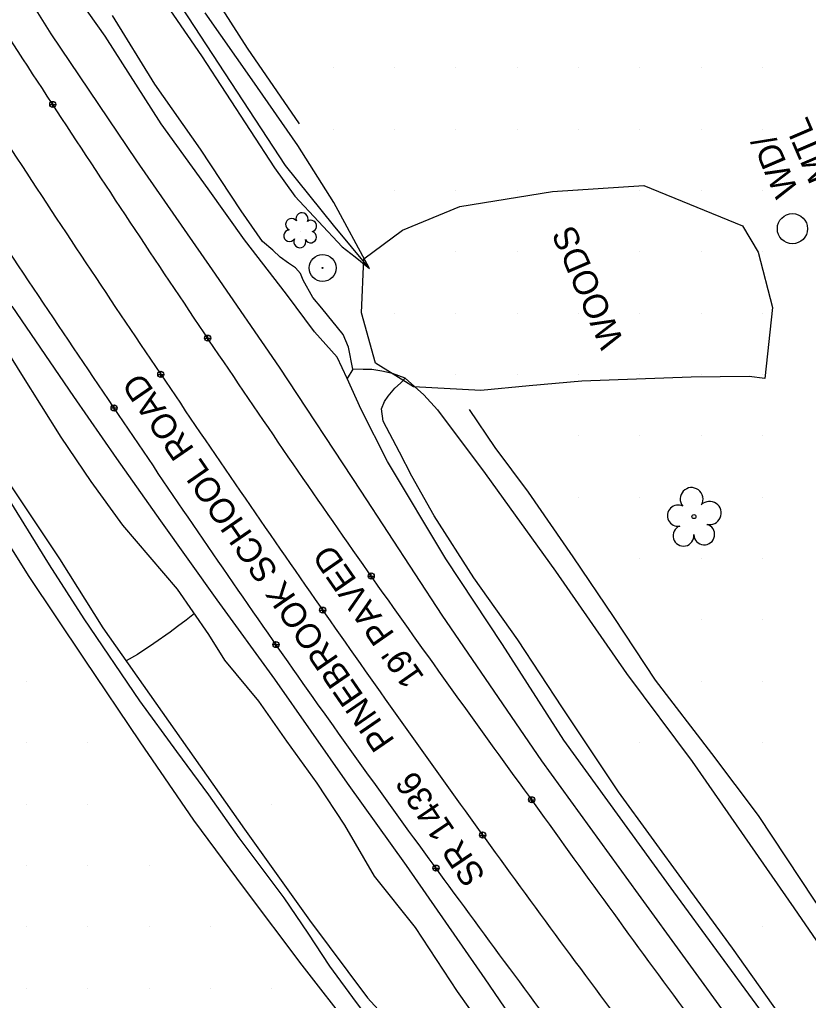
# Model space of a CAD drawing. Extents: x 1548934 to 1561348, y 809680 to 824075.
# Drawn here: x 1552078.9 to 1552207.5, y 810117.9 to 810277.8 of the extents above; entities that cross this region are included whole.
import ezdxf

# ---------------------------------------------------------------- set-up
doc = ezdxf.new("R2010")
doc.units = 0
for name, color, linetype in [('Default', 7, 'Continuous'), ('E_NCDOT_Vertical_Profile_Ground_Line', 7, 'Continuous'), ('Exist DTM QL2 LIDAR Elevation Point', 7, 'Continuous'), ('Exist Other Culture Sign Post CELL', 7, 'Continuous'), ('Exist Other Culture Sign Post Text', 7, 'Continuous'), ('Exist Roads EOP Text', 7, 'Continuous'), ('Exist Vegetation Shrub CELL', 7, 'Continuous'), ('Exist Vegetation Tree CELL', 7, 'Continuous'), ('Exist Vegetation Woods Line', 7, 'Continuous'), ('Exist Vegetation Woods Line Text', 7, 'Continuous'), ('P_NCDOT_Horizontal_Alignment_Tick_Large', 7, 'Continuous'), ('P_NCDOT_Vertical_Profile_Grade_Minor_Road', 7, 'Continuous'), ('PH Exist DTM Breakline', 7, 'Continuous')]:
    doc.layers.add(name, color=color, linetype=linetype)

# ---------------------------------------------------------------- blocks, each defined once
blk = doc.blocks.new('SurveyPointCell')
at = {"layer": 'Default'}
for p, q in [((-0.5, 0), (0.5, 0)), ((0, -0.5), (0, 0.5))]:
    blk.add_line(p, q, dxfattribs=at)
blk.add_circle((0, 0), 0.5, dxfattribs=at)

msp = doc.modelspace()

# ---------------------------------------------------------------- linework, layer by layer
at = {"layer": 'E_NCDOT_Vertical_Profile_Ground_Line'}
for points in [[(1552269.12, 810011.85), (1552259.92, 810023.16), (1552240.77, 810045.39), (1552214.34, 810080.42), (1552187.87, 810115.32), (1552162.13, 810150.99), (1552135.64, 810187.58), (1552109.72, 810225.45), (1552084.15, 810264.06), (1552058.91, 810303.06), (1552035.06, 810342.6), (1552011.64, 810381.93), (1551989.04, 810421.64), (1551966.75, 810462.54), (1551944.7, 810504.81), (1551922.38, 810547.42), (1551904.22, 810585.98), (1551891.94, 810609.51), (1551888.01, 810619.12)], [(1552253.41, 809998.89), (1552244.07, 810010.35), (1552226, 810034.01), (1552199.08, 810069.05), (1552172.73, 810104.35), (1552146.5, 810139.67), (1552120.17, 810176.34), (1552094.24, 810214.53), (1552068.08, 810253.47), (1552042.84, 810293.18), (1552018.16, 810332.72), (1551995.31, 810372.57), (1551972.35, 810412.52), (1551950.07, 810453.78), (1551927.46, 810496.24), (1551905.62, 810539.48), (1551886.94, 810576.33), (1551876.35, 810599.17), (1551872.14, 810607.03)]]:
    msp.add_open_spline(points, degree=3, dxfattribs=at)
at = {"layer": 'Exist DTM QL2 LIDAR Elevation Point'}
for p, q in [((1552130.03, 810269.95), (1552130.03, 810269.95)), ((1552140.03, 810269.95), (1552140.03, 810269.95)), ((1552150.03, 810269.95), (1552150.03, 810269.95)), ((1552160.03, 810269.95), (1552160.03, 810269.95)), ((1552170.03, 810269.95), (1552170.03, 810269.95)), ((1552180.03, 810269.95), (1552180.03, 810269.95)), ((1552190.03, 810269.95), (1552190.03, 810269.95)), ((1552200.03, 810269.95), (1552200.03, 810269.95)), ((1552130.03, 810259.95), (1552130.03, 810259.95)), ((1552140.03, 810259.95), (1552140.03, 810259.95)), ((1552150.03, 810259.95), (1552150.03, 810259.95)), ((1552160.03, 810259.95), (1552160.03, 810259.95)), ((1552170.03, 810259.95), (1552170.03, 810259.95)), ((1552180.03, 810259.95), (1552180.03, 810259.95)), ((1552190.03, 810259.95), (1552190.03, 810259.95)), ((1552200.03, 810259.95), (1552200.03, 810259.95)), ((1552140.03, 810249.95), (1552140.03, 810249.95)), ((1552150.03, 810249.95), (1552150.03, 810249.95)), ((1552160.03, 810249.95), (1552160.03, 810249.95)), ((1552170.03, 810249.95), (1552170.03, 810249.95)), ((1552180.03, 810249.95), (1552180.03, 810249.95)), ((1552190.03, 810249.95), (1552190.03, 810249.95)), ((1552200.03, 810249.95), (1552200.03, 810249.95)), ((1552150.03, 810239.95), (1552150.03, 810239.95)), ((1552160.03, 810239.95), (1552160.03, 810239.95)), ((1552170.03, 810239.95), (1552170.03, 810239.95)), ((1552180.03, 810239.95), (1552180.03, 810239.95)), ((1552190.03, 810239.95), (1552190.03, 810239.95)), ((1552200.03, 810239.95), (1552200.03, 810239.95)), ((1552140.03, 810229.95), (1552140.03, 810229.95)), ((1552150.03, 810229.95), (1552150.03, 810229.95)), ((1552160.03, 810229.95), (1552160.03, 810229.95)), ((1552170.03, 810229.95), (1552170.03, 810229.95)), ((1552180.03, 810229.95), (1552180.03, 810229.95)), ((1552190.03, 810229.95), (1552190.03, 810229.95)), ((1552200.03, 810229.95), (1552200.03, 810229.95)), ((1552150.03, 810219.95), (1552150.03, 810219.95)), ((1552160.03, 810219.95), (1552160.03, 810219.95)), ((1552170.03, 810219.95), (1552170.03, 810219.95)), ((1552180.03, 810219.95), (1552180.03, 810219.95)), ((1552190.03, 810219.95), (1552190.03, 810219.95)), ((1552200.03, 810219.95), (1552200.03, 810219.95)), ((1552170.03, 810209.95), (1552170.03, 810209.95)), ((1552180.03, 810209.95), (1552180.03, 810209.95)), ((1552190.03, 810209.95), (1552190.03, 810209.95)), ((1552200.03, 810209.95), (1552200.03, 810209.95)), ((1552170.03, 810199.95), (1552170.03, 810199.95)), ((1552180.03, 810199.95), (1552180.03, 810199.95)), ((1552190.03, 810199.95), (1552190.03, 810199.95)), ((1552200.03, 810199.95), (1552200.03, 810199.95)), ((1552180.03, 810189.95), (1552180.03, 810189.95)), ((1552190.03, 810189.95), (1552190.03, 810189.95)), ((1552200.03, 810189.95), (1552200.03, 810189.95)), ((1552190.03, 810179.95), (1552190.03, 810179.95)), ((1552200.03, 810179.95), (1552200.03, 810179.95)), ((1552080.03, 810169.94), (1552080.03, 810169.94)), ((1552190.03, 810169.94), (1552190.03, 810169.94)), ((1552200.03, 810169.94), (1552200.03, 810169.94)), ((1552080.03, 810159.94), (1552080.03, 810159.94)), ((1552090.03, 810159.94), (1552090.03, 810159.94)), ((1552180.03, 810159.94), (1552180.03, 810159.94)), ((1552200.03, 810159.94), (1552200.03, 810159.94)), ((1552080.03, 810149.94), (1552080.03, 810149.94)), ((1552090.03, 810149.94), (1552090.03, 810149.94)), ((1552120.03, 810149.94), (1552120.03, 810149.94)), ((1552080.03, 810139.94), (1552080.03, 810139.94)), ((1552090.03, 810139.94), (1552090.03, 810139.94)), ((1552100.03, 810139.94), (1552100.03, 810139.94)), ((1552080.03, 810129.94), (1552080.03, 810129.94)), ((1552090.03, 810129.94), (1552090.03, 810129.94)), ((1552100.03, 810129.94), (1552100.03, 810129.94)), ((1552110.03, 810129.94), (1552110.03, 810129.94)), ((1552200.03, 810129.94), (1552200.03, 810129.94)), ((1552080.03, 810119.94), (1552080.03, 810119.94)), ((1552090.03, 810119.94), (1552090.03, 810119.94)), ((1552100.03, 810119.94), (1552100.03, 810119.94)), ((1552110.03, 810119.94), (1552110.03, 810119.94)), ((1552120.03, 810119.94), (1552120.03, 810119.94))]:
    msp.add_line(p, q, dxfattribs=at)
at = {"layer": 'Exist Other Culture Sign Post CELL'}
msp.add_circle((1552204.89, 810243.72), 2.46, dxfattribs=at)
at = {"layer": 'Exist Vegetation Shrub CELL'}
msp.add_line((1552124.72, 810243.29), (1552124.72, 810243.29), dxfattribs=at)
for centre, radius, start, end in [((1552123.24, 810244.41), 0.968, 35.8908, 245.4216), ((1552124.95, 810245.33), 0.99, 334.8391, 200.4717), ((1552126.39, 810244.16), 0.929, 284.4567, 126.0861), ((1552122.92, 810242.58), 0.955, 95.1099, 327.9534), ((1552126.36, 810242.36), 0.937, 204.9913, 73.4601), ((1552124.59, 810241.6), 0.984, 151.2797, 21.387)]:
    msp.add_arc(centre, radius, start, end, dxfattribs=at)
at = {"layer": 'Exist Vegetation Tree CELL'}
msp.add_line((1552188.83, 810196.79), (1552188.83, 810196.79), dxfattribs=at)
msp.add_circle((1552188.83, 810196.79), 0.326, dxfattribs=at)
for centre, radius, start, end in [((1552188.45, 810199.66), 1.86, 330.1651, 219.7134), ((1552186.23, 810196.94), 1.73, 62.6636, 279.3457), ((1552191.38, 810197.38), 1.9, 257.1011, 134.1999), ((1552187.13, 810193.67), 1.69, 111.5671, 6.231), ((1552190.51, 810193.89), 1.7, 181.2822, 74.56)]:
    msp.add_arc(centre, radius, start, end, dxfattribs=at)
at = {"layer": 'Exist Vegetation Woods Line'}
msp.add_lwpolyline([(1552196.73, 810244.18), (1552199.3, 810239.89), (1552201.66, 810230.85), (1552200.4, 810219.3), (1552197.86, 810219.61), (1552188.36, 810219.51), (1552170.55, 810218.88), (1552161.99, 810218.08), (1552154.1, 810217.35), (1552143.13, 810217.94), (1552136.9, 810221.79), (1552134.66, 810230.01), (1552135, 810238.8), (1552141.3, 810243.48), (1552150.68, 810247.35), (1552165.77, 810249.78), (1552180.68, 810250.76), (1552196.73, 810244.18)], dxfattribs=at)
at = {"layer": 'P_NCDOT_Horizontal_Alignment_Tick_Large'}
for radius in [2.2, 0.0707]:
    msp.add_circle((1552128.3, 810237.32), radius, dxfattribs=at)
at = {"layer": 'P_NCDOT_Vertical_Profile_Grade_Minor_Road'}
msp.add_open_spline([(1551879.82, 810614.21), (1551884.04, 810605.38), (1551895.16, 810581.81), (1551913.82, 810543.91), (1551935.87, 810500.72), (1551958.31, 810458.4), (1551980.95, 810417.47), (1552003.45, 810377.53), (1552026.54, 810337.94), (1552050.88, 810298.39), (1552075.93, 810258.79), (1552101.83, 810219.9), (1552127.9, 810181.92), (1552154.01, 810145.19), (1552180.07, 810109.84), (1552206.52, 810074.71), (1552233.37, 810039.85), (1552251.61, 810016.53), (1552260.84, 810005.28)], degree=3, dxfattribs=at)
at = {"layer": 'PH Exist DTM Breakline'}
for points in [[(1552032.2, 810387.99), (1552038.28, 810377.65), (1552045.1, 810368.91), (1552058.76, 810347.89), (1552069.49, 810331.08), (1552076.13, 810321.01), (1552084.31, 810307.96), (1552094.24, 810292.72), (1552108.55, 810271.88), (1552120.44, 810253.63), (1552123.77, 810249.02), (1552131.49, 810240.77), (1552133.63, 810239.14), (1552135.93, 810237.21)], [(1552070.9, 810296.43), (1552083.99, 810275.5), (1552097.97, 810254.77), (1552110.28, 810237.04), (1552121.21, 810221.14), (1552134.52, 810200.95), (1552147.71, 810180.72), (1552163.96, 810156.98), (1552179.72, 810135.27), (1552195.09, 810114.14), (1552208.76, 810095.28), (1552229.1, 810067.78), (1552247.96, 810043.42), (1552263.84, 810022.89), (1552266.43, 810019.8), (1552267.45, 810018.79), (1552268.93, 810018), (1552270.68, 810017.79), (1552272.99, 810017.84), (1552278.9, 810019.9)], [(1552199.57, 810116.5), (1552185.58, 810135.61), (1552167.6, 810160.36), (1552157.62, 810175.93), (1552148.38, 810189.92), (1552138.89, 810205.79), (1552134.56, 810214.23), (1552132.33, 810219.3), (1552130.68, 810222.78), (1552126.99, 810226.9), (1552122.41, 810233.04), (1552115.54, 810241.9), (1552109.65, 810250.2), (1552101.98, 810260.8), (1552092.86, 810275.13), (1552084.32, 810287.15)], [(1552135.93, 810237.21), (1552130.05, 810244.32), (1552122.27, 810254.04), (1552113.38, 810267.56), (1552103.37, 810282.88)], [(1552110.55, 810281.68), (1552115.98, 810273.15), (1552124.46, 810260.83)], [(1552133.24, 810220.82), (1552132.54, 810224.43), (1552131.67, 810226.49), (1552128.17, 810230.76), (1552126.69, 810232.52), (1552125.15, 810235.34), (1552124.72, 810236.4), (1552123.89, 810237.35), (1552122.76, 810238.12), (1552121.39, 810239.07), (1552120.17, 810240.24), (1552118.49, 810241.66), (1552115.02, 810246.61), (1552108.39, 810256.67), (1552100.96, 810267.3), (1552094.06, 810278.47)], [(1552135.93, 810237.21), (1552130.14, 810248), (1552124.24, 810257.26), (1552116.79, 810267.96), (1552109.15, 810278.89)], [(1552031.09, 810258.86), (1552034.12, 810253.01), (1552038.46, 810246.99), (1552043.38, 810240.62), (1552053.3, 810226.91), (1552065.13, 810210.65), (1552072.2, 810200.07), (1552080.28, 810187.2), (1552089.43, 810173.57), (1552098.48, 810160.06), (1552107.27, 810147.29), (1552115.52, 810136.18), (1552124.92, 810123.69), (1552133.11, 810113.15), (1552140.37, 810103.29), (1552145.12, 810096.11), (1552145.71, 810095.17), (1552146.69, 810090.84)], [(1552156.32, 810110.91), (1552150.29, 810119.36), (1552143.44, 810129.83), (1552136.74, 810138.2), (1552131.9, 810146.49), (1552127.41, 810153.34), (1552122.48, 810160.19), (1552117.91, 810166.69), (1552112.35, 810173.37), (1552109.77, 810177.56), (1552104.66, 810184.94), (1552095.71, 810195.42), (1552090.59, 810202.53), (1552085.7, 810209.72), (1552079.25, 810219.96), (1552071.17, 810232.95)], [(1552158.97, 810089.08), (1552161.06, 810093.49), (1552162.17, 810096.81), (1552163.17, 810100.05), (1552163.66, 810103.74), (1552163.44, 810106.4), (1552162.57, 810109.26), (1552161.08, 810112.2), (1552154.8, 810121.44), (1552141.96, 810139.91), (1552132.34, 810153.32), (1552120.52, 810170.3), (1552111.12, 810183.22), (1552101.94, 810196.1), (1552094.74, 810206.28), (1552087.72, 810216.38), (1552077.67, 810231.11)], [(1552141.76, 810219.33), (1552139.72, 810220.13), (1552137.94, 810220.48), (1552136.32, 810220.75), (1552134.91, 810220.79), (1552133.24, 810220.82), (1552132.33, 810219.3)], [(1552203.84, 810114.1), (1552195.14, 810126.42), (1552187.27, 810137.16), (1552176.56, 810151.95), (1552167.42, 810165.64), (1552160.12, 810176.68), (1552152.96, 810186.81), (1552146.49, 810196.89), (1552142.83, 810203.38), (1552140.85, 810207.3), (1552138.19, 810212.36), (1552137.92, 810214.37), (1552138.39, 810215.57), (1552138.99, 810216.41), (1552140.1, 810217.7), (1552141, 810218.56), (1552141.76, 810219.33), (1552144.78, 810216.64), (1552147.02, 810214.19)], [(1552147.02, 810214.19), (1552154.79, 810203.81), (1552166.26, 810187.92), (1552177.85, 810171.19), (1552188.57, 810156.89), (1552205.11, 810133.01), (1552216.56, 810116.34)], [(1552223.36, 810113.03), (1552214.45, 810125.58), (1552208.48, 810134.28), (1552199.37, 810148.07), (1552191.77, 810158.16), (1552182.59, 810170.13), (1552175.84, 810180.34), (1552169.15, 810190.21), (1552161.85, 810200.77), (1552156.44, 810208.05), (1552152.25, 810214.27)], [(1552076.82, 810202.78), (1552085.4, 810189.91), (1552092.48, 810178.66), (1552102.12, 810164.93), (1552115.55, 810145.82), (1552126.18, 810130.99), (1552135.64, 810118.33), (1552137.94, 810115.81)], [(1552149.19, 810093.18), (1552147.66, 810097.47), (1552145.78, 810101.08), (1552143.54, 810104.12), (1552140.85, 810108.45), (1552138.03, 810112.03), (1552133.85, 810117.61), (1552129.49, 810123.53), (1552125.94, 810128.89), (1552122.04, 810134.63), (1552114.71, 810144.42), (1552109.77, 810151.43), (1552104.51, 810158.52), (1552098.53, 810166.75), (1552089.43, 810180.1), (1552083.79, 810188.91), (1552077.39, 810199.33)], [(1552107.39, 810181), (1552106.08, 810179.93), (1552104.62, 810178.86), (1552103.45, 810177.95), (1552100.77, 810176.1), (1552098.12, 810174.3), (1552096.27, 810173.27)]]:
    msp.add_lwpolyline(points, dxfattribs=at)

# ---------------------------------------------------------------- block references
at = {"layer": 'Default'}
for p in [(1552084.31, 810263.97), (1552109.57, 810225.89), (1552101.92, 810219.97), (1552094.31, 810214.5), (1552136.22, 810187.1), (1552128.31, 810181.55), (1552120.7, 810175.93), (1552162.38, 810150.63), (1552154.39, 810144.89), (1552146.78, 810139.49)]:
    msp.add_blockref('SurveyPointCell', p, dxfattribs=at)

# ---------------------------------------------------------------- texts
at = {"layer": 'Exist Other Culture Sign Post Text'}
for s, p in [('MTL', (1552211.49, 810252.28)), ('WD/', (1552205.95, 810249.9))]:
    msp.add_text(s, height=4.02, rotation=113.1736, dxfattribs=at).set_placement(p)
at = {"layer": 'Exist Roads EOP Text'}
for s, rotation, p in [('PINEBROOK SCHOOL ROAD', 124.5425, (1552140.17, 810160.26)), ("19' PAVED", 124.8763, (1552144.99, 810170.63)), ('SR 1436', 124.0536, (1552154.99, 810138.26))]:
    msp.add_text(s, height=4.02, rotation=rotation, dxfattribs=at).set_placement(p)
at = {"layer": 'Exist Vegetation Woods Line Text'}
msp.add_text('WOODS', height=4.02, rotation=113.1736, dxfattribs=at).set_placement((1552177.47, 810225.3))

doc.saveas('drawing.dxf')
